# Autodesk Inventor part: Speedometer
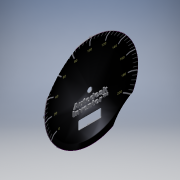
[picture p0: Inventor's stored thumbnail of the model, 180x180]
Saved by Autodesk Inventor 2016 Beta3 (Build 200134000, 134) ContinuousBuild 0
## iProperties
Company: Autodesk, Inc.
Shininess: 64.0
Length Units: 11272
Angle Units: 11279
Time Units: 11290
Mass Units: 11286
Length Display Precision: 3
Angle Display Precision: 2
Compacted: True
Part Number: Speedometer
Document SubType Name: Modeling
Created: 2002-09
Stock Number: PRL-534-B
Density: 1 g/cm^3
Mass: 7.02363 g
Surface Area: 170.355 cm^2
Volume: 7.02363 cm^3
Material: Generic
Appearance: Default
Designer: Autodesk, Inc.
Density: 0.0
Volumn: 0.0
Area: 0.0
PropertySet Name: Model Information
Control State: 0
Master: False
Checked Out: False
Author: Autodesk, Inc.
Revision Number: A
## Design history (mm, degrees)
sketch "Sketch1"
  geometry: L1 (0, 0)-(-45.72, 0); L2 (-45.72, 0)-(-50.8, 1.849); L3 (0, -26.18)-(0, 27.22) reference; L4 (-44.342, 19.592)-(-58.225, -18.551)
  constraints: 6 end point, 1 horizontal, 1 perpendicular, 1 point on line
  dimensions: "d0" = 45.72 distance of L1.start L1.end; "d1" = 50.8 horizontal distance of L1.start L2.end; "d2" = 160 deg angle of L1 L2
feature "RevolutionSrf1" dims angle "d3" = 90 deg
fillet "Fillet1" dims "d4" = 3.175
thicken "Thicken1" dims "d5" = 0.762
sketch "Sketch2"
  geometry: L1 (-1.27, 65.322)-(-1.27, 16.574); L2 (1.27, 16.574)-(1.27, 65.322); L3 (0, 0)-(0, 66.507); L4 (-10.821, 12.617)-(-45.291, 47.088); L5 (-47.088, 45.291)-(-12.617, 10.821); L6 (-16.574, 1.27)-(-65.322, 1.27); L7 (-65.322, -1.27)-(-16.574, -1.27); L8 (-12.617, -10.821)-(-47.088, -45.291); L9 (-45.291, -47.088)-(-10.821, -12.617); L10 (-1.27, -16.574)-(-1.27, -65.322); L11 (1.27, -65.322)-(1.27, -16.574); L12 (10.821, -12.617)-(45.291, -47.088); L13 (47.088, -45.291)-(12.617, -10.821); L14 (16.574, -1.27)-(65.322, -1.27); L15 (65.322, 1.27)-(16.574, 1.27); L16 (12.617, 10.821)-(47.088, 45.291); L17 (45.291, 47.088)-(10.821, 12.617); C1 r 14.082 at (0, 0); C2 r 45.16 at (0, 0) reference; A1 r 65.334 centre (0, 0) between (1.27, 65.322) and (-1.27, 65.322); A2 r 65.334 centre (0, 0) between (-45.291, 47.088) and (-47.088, 45.291); A3 r 65.334 centre (0, 0) between (-65.322, 1.27) and (-65.322, -1.27); A4 r 65.334 centre (0, 0) between (-47.088, -45.291) and (-45.291, -47.088); A5 r 65.334 centre (0, 0) between (-1.27, -65.322) and (1.27, -65.322); A6 r 65.334 centre (0, 0) between (45.291, -47.088) and (47.088, -45.291); A7 r 65.334 centre (0, 0) between (65.322, -1.27) and (65.322, 1.27); A8 r 65.334 centre (0, 0) between (47.088, 45.291) and (45.291, 47.088); A9 r 16.622 centre (0, 0) between (-12.617, 10.821) and (-16.574, 1.27); A10 r 16.622 centre (0, 0) between (-16.574, -1.27) and (-12.617, -10.821); A11 r 16.622 centre (0, 0) between (-10.821, -12.617) and (-1.27, -16.574); A12 r 16.622 centre (0, 0) between (1.27, -16.574) and (10.821, -12.617); A13 r 16.622 centre (0, 0) between (12.617, -10.821) and (16.574, -1.27); A14 r 16.622 centre (0, 0) between (16.574, 1.27) and (12.617, 10.821); A15 r 16.622 centre (0, 0) between (10.821, 12.617) and (1.27, 16.574); A16 r 16.622 centre (0, 0) between (-1.27, 16.574) and (-10.821, 12.617)
  constraints: 34 end point, 32 point on circle, 17 centre point, 3 coincident, 2 parallel, 1 vertical, 65 other
  dimensions: "d101" = 2.54 distance between parallel lines of L2 L1; "d105" = 360 deg dimension on A9.centre L2.start (derived)
feature "Sculpt1"
fillet "Fillet8" dims "d67" = 2.54
fillet "Fillet9" dims "d68" = 0.3175
fillet "Fillet10" dims "d69" = 0.3175
workplane "Work Plane1"
sketch "Sketch8"
  geometry: L1 (-12.7, -32.385)-(12.7, -32.385); L2 (12.7, -32.385)-(12.7, -22.86); L3 (12.7, -22.86)-(-12.7, -22.86); L4 (-12.7, -22.86)-(-12.7, -32.385); 1 further point
  constraints: 8 end point, 2 parallel, 1 horizontal, 1 perpendicular
  dimensions: "d109" = 25.4 distance of L1.start L1.end; "d110" = 9.525 distance of L1.end L2.end; "d111" = 12.7 distance from line of L4 point (0, 0) (derived); "d112" = 22.86 distance from line of point (0, 0) L3
extrude "Extrusion3" cut sketch "Sketch8" stored distance "d113" = 25.4; taper "d114" = 0 deg
fillet "Fillet2" dims "d53" = 1.27
sketch "Sketch5"
  geometry: L1 (25.429, 19.589)-(-25.429, 19.589); L2 (-25.429, 19.589)-(-25.429, 1.055); L3 (-25.429, 1.055)-(25.429, 1.055); L4 (25.429, 1.055)-(25.429, 19.589); L5 (0, 1.055)-(0, 22.86)
  constraints: 2 end point, 1 midpoint, 1 perpendicular, 2 other
emboss "Emboss1" sketch "Sketch5" dims "d25" = 1.27, "d26" = 0
sketch "Sketch9"
  geometry: C1 r 45.16 at (0, 0) reference; C2 r 2.54 at (0, 0)
  constraints: 1 centre point, 1 coincident
  dimensions: "d115" = 5.08 diameter of C2
extrude "Extrusion4" cut sketch "Sketch9" stored distance "d116" = 25.4; taper "d117" = 0 deg
fillet "Fillet3" dims "d54" = 0.3175
body "Solid1"
feature "Decal1"
feature "Decal3"
body "Srf1"
sketch "Sketch3"
  geometry: L1 (-50.8, 0)-(50.8, 0); L2 (-50.8, 50.8)-(50.8, 50.8); L3 (50.8, 50.8)-(50.8, -50.8); L4 (50.8, -50.8)-(-50.8, -50.8); L5 (-50.8, -50.8)-(-50.8, 50.8); L6 (71.12, 0)-(-71.12, 0) reference; L7 (0, -71.12)-(0, 71.12) reference; 2 further points; 1 other entity
  constraints: 2 end point, 1 coincident, 1 midpoint, 2 other
  dimensions: "d164" = 101.6 distance between parallel lines of L3 L5; "d165" = 50.8 distance between parallel lines of L7 L5 (derived); "d166" = 50.8 distance between parallel lines of L6 L2 (derived)
body "Srf3"
body "Srf4"
body "Srf5"
body "Srf2"
sketch "Sketch10"
  geometry: L1 (4.655, 10.901)-(25.518, 10.901); L2 (25.518, 10.901)-(25.518, 6.004); L3 (25.518, 6.004)-(4.655, 6.004); L4 (4.655, 6.004)-(4.655, 10.901); 1 further point; 1 other entity
  constraints: 2 other
node "Image3"
node "Image4"
extrude_surface "ExtrusionSrf1" dims "d93" = 25.4, "d94" = 0
extrude_surface "ExtrusionSrf2" dims "d95" = 25.4, "d96" = 0
feature "OffsetSrf2" dims "d97" = 0.762, "d98" = 0.762
feature "RevolutionSrf2" dims angle "d99" = 90 deg
other parameters: "d6" = 2.54, "d17" = 12.7, "d84" = 2.54, "d86" = 2.54 (derived)
